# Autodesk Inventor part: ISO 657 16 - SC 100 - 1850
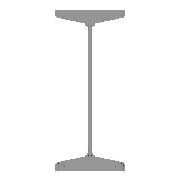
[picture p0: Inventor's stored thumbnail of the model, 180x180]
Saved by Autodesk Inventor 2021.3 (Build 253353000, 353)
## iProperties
IsCustomPart: 1
_CCFamilyMember: 1
_CCFamilyDisplayName: ISO 657/16 - 1980 - Poutres en acier laminées à chaud - Partie 16: profilés en H (série métrique) - Cotes et propriétés de section
_FrameMemberDoc: Frame Member File
_Version: 25.0.0
_GetPNFromCC: 1
Created: 2018-07
Part Number: ISO 657 16 - SC 100 - 1850
Material: Acier, doux
Description: Poutres en acier laminées à chaud - Partie 16: profilés en H (série métrique) - Cotes et propriétés de section
Document SubType Name: Modeling
Standard: ISO
Designer: Fabian Perrée
Standard Revision: First edition 1980-02-15
Standards Organization: ISO
Language: fr-FR
Size Designation: SC 100
Categories: <MemberInstance><Categories><Category DisplayName="Profilés" InternalName="089c4875-fa83-4c05-b084-43b9cc11f5ed" Mnemonic="GRDR"><CategoryParameter DisplayName=
Stock Number: SC 100
Density: 7.85 g/cm^3
Appearance: Semi-poli
Mass: 36980.1 g
Surface Area: 10064.8 cm^2
Volume: 4710.84 cm^3
G_W: 100,000 mm
G_H: 100,000 mm
G_L: 1850,000 mm
+3996474A-F15E-4C0C-B350-EF0BE35A7832+DETAILDECOUPE6: Angle de coupe 90,00 deg
+49FB2D49-B789-45CC-8DEB-3E9423125D72+DETAILDECOUPE7: Angle de coupe 90,00 deg
Author: Fabian Perrée
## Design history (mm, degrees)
node "Plan de départ"
node "Plan de fin"
sketch "Esquisse"
  geometry: L1 (-3, 0)-(-3, -26.266); L2 (-13.33, -38.149)-(-44.835, -42.577); L3 (-50, -48.518)-(-50, -50); L4 (-50, -50)-(0, -50); L5 (-26.5, -50)-(-26.5, -40); L6 (-61.333, 0)-(81.777, 0); L7 (0, 0)-(0, -50); L8 (0, -60)-(0, 80); L9 (3, 0)-(3, -26.266); L10 (13.33, -38.149)-(44.835, -42.577); L11 (50, -48.518)-(50, -50); L12 (50, -50)-(0, -50); L13 (-3, 0)-(0, 0); L14 (-3, 0)-(-3, 26.266); L15 (-13.33, 38.149)-(-44.835, 42.577); L16 (-50, 48.518)-(-50, 50); L17 (-50, 50)-(0, 50); L18 (50, 48.518)-(50, 50); L19 (13.33, 38.149)-(44.835, 42.577); L20 (3, 0)-(3, 26.266); L21 (50, 50)-(0, 50); L22 (0, 108)-(0, -88) reference; L23 (-89.955, 0)-(110.399, 0) reference; A1 r 6 centre (-44, 48.518) between (-50, 48.518) and (-44.835, 42.577); A2 r 6 centre (44, 48.518) between (44.835, 42.577) and (50, 48.518); A3 r 6 centre (44, -48.518) between (50, -48.518) and (44.835, -42.577); A4 r 6 centre (-44, -48.518) between (-44.835, -42.577) and (-50, -48.518); A5 r 12 centre (-15, 26.266) between (-3, 26.266) and (-13.33, 38.149); A6 r 12 centre (15, 26.266) between (13.33, 38.149) and (3, 26.266); A7 r 12 centre (15, -26.266) between (3, -26.266) and (13.33, -38.149); A8 r 12 centre (-15, -26.266) between (-13.33, -38.149) and (-3, -26.266); 14 further points
  constraints: 42 end point, 24 point on line, 17 symmetric about line, 16 point on circle, 16 tangent, 8 centre point, 6 equal radius, 4 collinear, 2 perpendicular, 12 other
  dimensions: "d1" = 10 vertical distance of L3.end L5.end (= G_T1); "d2" = 23.5 distance between parallel lines of L5 L3 (= -0.25 x G_T + 0.25 x G_W); "d3" = 3 distance between parallel lines of L1 L7 (= 0.5 x G_T); "d4" = 50 distance between parallel lines of L7 L3 (= 0.5 x G_W); "d9" = 50 distance from line of L1.start L4 (= 0.5 x G_H); "d14" = 98 deg angle of L2 L1 (= G_NG); "d15" = 6 radius of A1 (= G_ER); "d16" = 12 radius of A5 (= G_IR)
extrude "Corps" new body sketch "Esquisse" stored distance "d5" = 1850 (= G_L); taper "d6" = 0 deg
node "Driven Length"
  sketch "Sketch3"
    geometry: L1 (0, 0)-(10, 0) reference
    constraints: 2 end point, 1 horizontal
  workplane "Work Plane3"
  sketch "Sketch4"
    geometry: L1 (-2, -50)-(12, -50) reference; L2 (-2, 1800)-(12, 1800) reference
    dimensions: "d20" = 1850 distance between parallel lines of L1 L2 (derived)
node "Plan de construction17"
feature "Scission5"
node "Plan de construction18"
feature "Scission6"
body "Solid1"
other parameters: "G_W" = 100 (= G_H) [user parameter; used in 2 equation terms], "G_H" = 100 [user parameter; used in 2 equation terms], "G_T" = 6 [user parameter; used in 2 equation terms], "G_T1" = 10 [user parameter; used in 1 equation term], "G_L" = 1850 (= d20) [user parameter; used in 1 equation term], "G_ER" = 6 [user parameter; used in 1 equation term], "G_IR" = 12 [user parameter; used in 1 equation term], "G_NG" = 98 deg [user parameter; used in 1 equation term], "d19" = 90 deg
